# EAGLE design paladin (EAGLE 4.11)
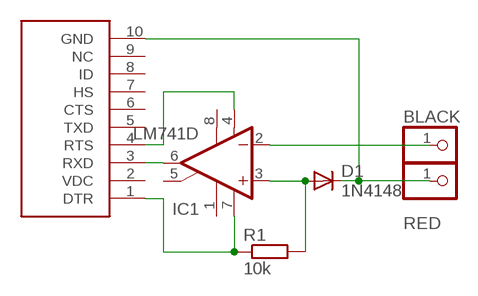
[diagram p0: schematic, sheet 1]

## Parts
BLACK  PINHD-1X1  [1X01]
D1  1N4148  PMLL4150  [SOD80C]
IC1  LM741D  [SO08]
R1  10k  R-EU_M0805  [M0805]
RED  PINHD-1X1  [1X01]
U$1  PALM  [PCON]

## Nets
GND: D1.C RED.1 U$1.10(GND)
N$1: IC1.6(OUT) U$1.3(RXD)
N$2: D1.A IC1.3(+IN) R1.2
N$3: BLACK.1 IC1.2(-IN)
N$5: IC1.4(V-) U$1.4(RTS)
N$7: IC1.7(V+) R1.1 U$1.1(DTR)
Unconnected: IC1.1(ON1) IC1.5(ON2) IC1.8(OPT) U$1.2(VDC) U$1.5(TXD) U$1.6(CTS) U$1.7(HS) U$1.8(ID) U$1.9(NC)

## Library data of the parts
BLACK RED = pinhead:PINHD-1X1: PIN HEADER
D1 = diode:PMLL4150: DIODE
IC1 = linear:*741: OP AMP
R1 = rcl:R-EU_: RESISTOR, European symbol
U$1 = palm:PALM

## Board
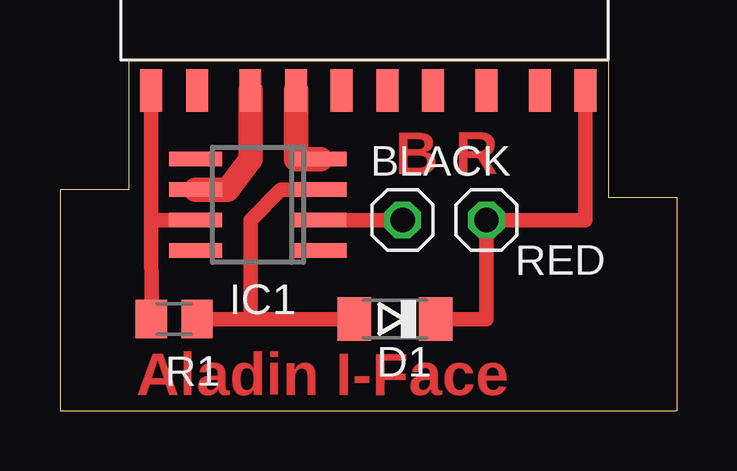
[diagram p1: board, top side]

Size 25.72 x 14.6 mm. Coordinates in mm from the lower left corner, seen from the top.
Outline: 2.86,14.6 2.86,9.21 0,9.21 0,0 25.72,0 25.72,8.89 22.86,8.89 22.86,14.6 2.86,14.6
Copper layers 1: Top 0.035mm
Design rules "default": minimum track width 10mil, minimum drill 24mil, track to track 8mil, track to pad 8mil, pad to pad 8mil, via to via 8mil, smd to smd 8mil, copper to edge 40mil, drill to drill 8mil, minimum pad ring 10mil, minimum via ring 8mil, stop-mask expansion 4mil, vias tented up to drill 0mil, thermal gap 10mil

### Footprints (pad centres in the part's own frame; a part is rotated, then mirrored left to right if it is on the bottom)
1X01 = drill 1.016 octagon: 1 0,0
SOD80C = smd 1.4 x 1.8: A 1.7,0; C -1.7,0
SO08 = smd 0.6 x 2.2: 1 -1.905,-2.6; 2 -0.635,-2.6; 3 0.635,-2.6; 4 1.905,-2.6; 5 1.905,2.6; 6 0.635,2.6; 7 -0.635,2.6; 8 -1.905,2.6
M0805 = smd 1.3 x 1.6: 1 -0.95,0; 2 0.95,0
PCON = smd 0.914 x 1.778: 1 0,0; 2 1.905,0; 3 4.128,0; 4 6.032,0; 5 7.938,0; 6 9.842,0; 7 11.748,0; 8 13.97,0; 9 16.192,0; 10 18.098,0

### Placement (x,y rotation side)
BLACK  14.29,7.94 0 top
D1  13.97,3.81 180 top
IC1  8.25,8.57 90 top
R1  4.76,3.81 0 top
RED  17.78,7.94 0 top
U$1  3.81,13.33 0 top

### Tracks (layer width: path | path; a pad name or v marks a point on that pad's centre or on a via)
GND
  Top 0.61: U$1.10 21.91,7.94 RED.1 17.78,3.81 D1.C
N$1
  Top 1.016: IC1.6 6.99,9.21 7.94,10.48 U$1.3
N$2
  Top 0.61: IC1.3 9.21,9.21 7.94,7.94 7.94,3.81 | R1.2 7.94,3.81 | 7.94,3.81 D1.A
N$3
  Top 0.61: 10.8,7.94 IC1.2 BLACK.1
N$5
  Top 1.016: U$1.4 9.84,10.48 IC1.4
N$7
  Top 0.61: 3.81,7.94 IC1.7 | R1.1 3.81,7.94 | 3.81,7.94 U$1.1

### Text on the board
Top: B R | Aladin I-Face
